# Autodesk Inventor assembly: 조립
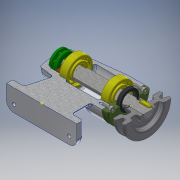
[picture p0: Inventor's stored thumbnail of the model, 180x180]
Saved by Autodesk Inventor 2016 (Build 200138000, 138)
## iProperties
Created: 2018-09
Part Number: 조립
Document SubType Name: Assembly
Designer: CAMTIC
Author: CAMTIC
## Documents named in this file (12)
- C:\Users\CAMTIC\Desktop\480907V1026\조립.iam
- C:\Users\CAMTIC\Desktop\480907V1026\본체.ipt
- C:\Users\CAMTIC\Desktop\480907V1026\V벨트풀리.ipt
- C:\Users\CAMTIC\Desktop\480907V1026\멈춤나사 M3.ipt
- C:\Users\CAMTIC\Desktop\480907V1026\베어링 6004.ipt
- C:\Users\CAMTIC\Desktop\480907V1026\베어링 51202.ipt
- C:\Users\CAMTIC\Desktop\480907V1026\볼트 M4.ipt
- C:\Users\CAMTIC\Desktop\480907V1026\어댑터슬리브.ipt
- C:\Users\CAMTIC\Desktop\480907V1026\오일 실.ipt
- C:\Users\CAMTIC\Desktop\480907V1026\축.ipt
- C:\Users\CAMTIC\Desktop\480907V1026\커버.ipt
- C:\Users\CAMTIC\Desktop\480907V1026\키 5 x 5 x 16.ipt
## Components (1 placed, 1 different names)
1. V벨트풀리:1
